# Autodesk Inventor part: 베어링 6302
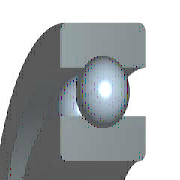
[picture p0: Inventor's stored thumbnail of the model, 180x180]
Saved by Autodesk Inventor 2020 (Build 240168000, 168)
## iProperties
IsCustomPart: 1
Created: 2012-02
Part Number: 베어링 6302
Material: 강철, 연강
Document SubType Name: Modeling
Standard: JIS B 1521
Designer: mdu-01
Standards Organization: JIS
Language: ko-KR
Size Designation: 6302 15x42x13
Categories: <MemberInstance><Categories><Category DisplayName="샤프트 부품" InternalName="7f7aeb1f-a693-4053-b835-cee3144e0d98" Mnemonic="SHFT"><Category DisplayName="베어링" Inter
Density: 1 g/cm^3
Appearance: 노란색
Author: mdu-01
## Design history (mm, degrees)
sketch "스케치" dims "d0" = 7.02 (= -0.26 x WD + 0.26 x BD)
  geometry: L1 (2.99, 14.25)-(10.01, 14.25); L2 (6.5, 14.25)-(6.5, 10.74); L3 (6.5, 14.25)-(6.5, 17.76); L4 (3.892, 11.901)-(0, 11.901); L5 (0, 7.5)-(13, 7.5); L6 (3.892, 16.599)-(0, 16.599); L7 (0, 21)-(13, 21); L8 (13, 7.5)-(13, 11.901); L9 (9.108, 11.901)-(13, 11.901); L10 (9.108, 16.599)-(13, 16.599); L11 (13, 21)-(13, 16.599); L12 (-1.4, 0)-(8.4, 0) reference; L13 (0, -0.3)-(0, 5.3) reference
  constraints: 22 end point, 4 point on line, 2 collinear, 2 perpendicular, 2 symmetric about line, 1 midpoint, 1 parallel, 14 other
  dimensions: "d9" = 15 diameter of L5 L12 (= WD); "d11" = 42 diameter of L7 L12 (= BD); "d12" = 13 distance between parallel lines of L8 L13 (= KB); "d13" = 23.802 diameter of L9 L12 (= 0.326 x BD + 0.674 x WD)
revolve "본체" stored, may be unused: angle "d6" = 90 deg
revolve "볼" stored, may be unused: angle "d7" = 90 deg
pattern_circular "IDS_ARRAYBALL[SIMPL:T]" dims angle "d3" = 360 deg
body "Solid1"
fillet "모깎기1" dims "d1" = 1 (= KRS)
other parameters: "WD" = 15 [user parameter; used in 5 equation terms], "BD" = 42 [user parameter; used in 5 equation terms], "KB" = 13 [user parameter; used in 1 equation term], "KRS" = 1 [user parameter; used in 1 equation term], "d4" = 0, "d5" = 0, "d8" = 0, "d14" = 0, "d15" = 0, "BBA" = 0 [user parameter], "BC0" = 5400000 [user parameter], "BC" = 1.14e+07 [user parameter], "BR" = 21 (= 0.5 x BD) [user parameter], "WR" = 7.5 (= 0.5 x WD) [user parameter]
